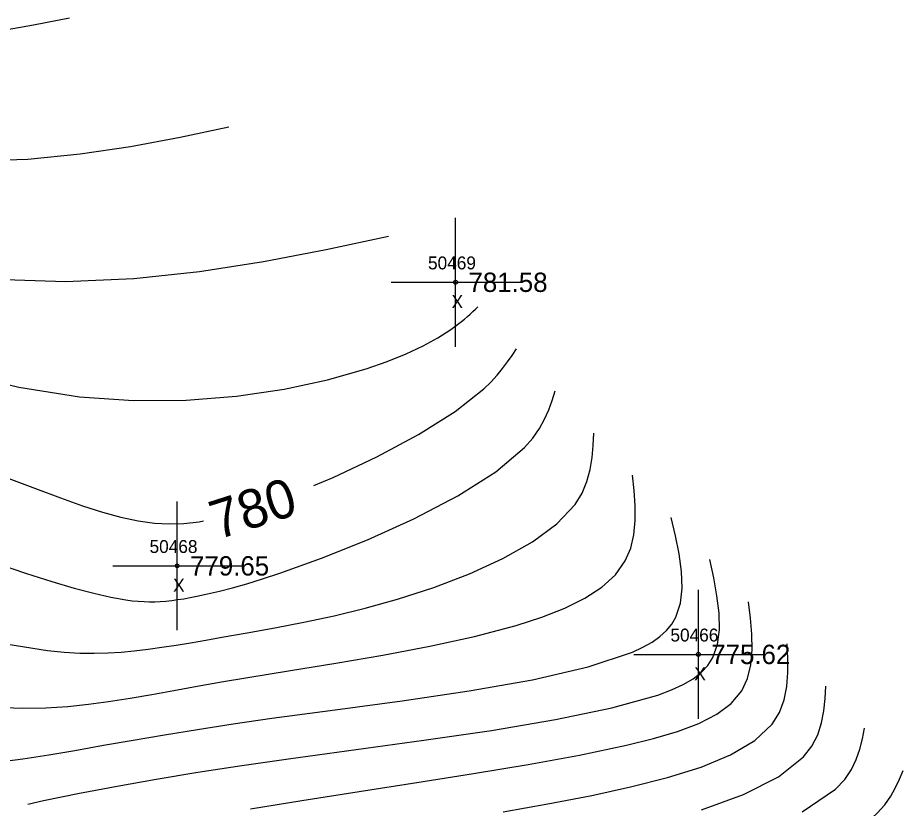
# Model space of a CAD drawing. Extents: x 1378535 to 1380697, y 997729 to 1000024.
# Drawn here: x 1379450.5 to 1379519.3, y 999255.8 to 999317.1 of the extents above; entities that cross this region are included whole.
import ezdxf

# ---------------------------------------------------------------- set-up
doc = ezdxf.new("R2010")
doc.units = 0
for name, color, linetype in [('RD_DTM_Major1', 7, 'Continuous'), ('RD_DTM_Major1_Lbl', 7, 'Continuous'), ('RD_DTM_Minor1', 7, 'Continuous'), ('RD_EX_Misc', 7, 'Continuous'), ('RD_EX_Misc_txCode', 7, 'Continuous'), ('RD_EX_TX_Misc_ELEV', 7, 'Continuous'), ('RD_SMD_Locator', 7, 'Continuous')]:
    doc.layers.add(name, color=color, linetype=linetype)

msp = doc.modelspace()

# ---------------------------------------------------------------- linework, layer by layer
at = {"layer": 'RD_DTM_Major1'}
for points in [[(1379473.511, 999280.806), (1379475.007, 999281.423), (1379478.414, 999283.027), (1379481.643, 999284.764), (1379484.48, 999286.551), (1379486.711, 999288.305), (1379487.261, 999288.841), (1379487.742, 999289.368), (1379488.168, 999289.886), (1379488.554, 999290.399), (1379488.911, 999290.909), (1379489.255, 999291.416)], [(1379445.979, 999282.807), (1379451.919, 999280.573), (1379453.855, 999279.857), (1379455.58, 999279.247), (1379457.135, 999278.743), (1379458.558, 999278.348), (1379459.889, 999278.065), (1379461.169, 999277.894), (1379462.299, 999277.839), (1379463.44, 999277.876), (1379464.611, 999278.004), (1379464.959, 999278.067)], [(1379451.323, 999256.11), (1379452.557, 999256.377), (1379455.348, 999256.947), (1379458.252, 999257.499), (1379461.298, 999258.038), (1379464.513, 999258.568), (1379467.927, 999259.093), (1379471.567, 999259.619), (1379482.041, 999261.05), (1379487.311, 999261.822), (1379492.265, 999262.653), (1379496.652, 999263.56), (1379500.218, 999264.562), (1379501.262, 999264.953), (1379502.168, 999265.368), (1379502.939, 999265.817), (1379503.58, 999266.311), (1379504.093, 999266.858), (1379504.483, 999267.469), (1379504.842, 999268.493), (1379504.985, 999269.649), (1379504.954, 999270.911), (1379504.793, 999272.252), (1379504.545, 999273.646), (1379504.253, 999275.066)], [(1379480.82, 999243.85), (1379481.655, 999244.004), (1379483.224, 999244.304), (1379484.868, 999244.629), (1379486.62, 999244.99), (1379491.785, 999246.124), (1379497.47, 999247.511), (1379503.228, 999249.107), (1379508.615, 999250.871), (1379513.185, 999252.761), (1379516.491, 999254.735), (1379517.23, 999255.392), (1379517.817, 999256.052), (1379518.282, 999256.716), (1379518.656, 999257.381), (1379518.969, 999258.048), (1379519.252, 999258.716)]]:
    msp.add_lwpolyline(points, dxfattribs=at)
at = {"layer": 'RD_DTM_Minor1'}
for points in [[(1379448.973, 999316.045), (1379451.781, 999316.552), (1379454.566, 999317.099)], [(1379447.1, 999305.987), (1379451.329, 999306.131), (1379455.384, 999306.531), (1379459.308, 999307.122), (1379463.145, 999307.841), (1379466.938, 999308.623)], [(1379448.717, 999296.812), (1379454.252, 999296.64), (1379459.549, 999296.865), (1379464.656, 999297.408), (1379469.62, 999298.188), (1379474.489, 999299.128), (1379479.31, 999300.147)], [(1379445.912, 999289.589), (1379450.634, 999288.449), (1379455.347, 999287.695), (1379459.526, 999287.402), (1379463.611, 999287.439), (1379467.531, 999287.754), (1379471.213, 999288.298), (1379474.583, 999289.019), (1379477.57, 999289.867), (1379479.22, 999290.442), (1379480.696, 999291.04), (1379482.004, 999291.654), (1379483.149, 999292.278), (1379484.138, 999292.904), (1379484.976, 999293.526), (1379485.212, 999293.721), (1379485.435, 999293.915), (1379485.649, 999294.108), (1379485.855, 999294.301), (1379486.057, 999294.493), (1379486.256, 999294.686)], [(1379449.003, 999274.74), (1379451.223, 999274.001), (1379453.189, 999273.376), (1379454.921, 999272.862), (1379456.443, 999272.455), (1379457.775, 999272.151), (1379458.939, 999271.945), (1379459.434, 999271.881), (1379459.901, 999271.836), (1379460.347, 999271.81), (1379460.775, 999271.799), (1379461.192, 999271.803), (1379461.602, 999271.821), (1379462.046, 999271.853), (1379462.493, 999271.9), (1379462.951, 999271.96), (1379463.424, 999272.035), (1379463.918, 999272.123), (1379464.44, 999272.226), (1379465.278, 999272.406), (1379466.198, 999272.624), (1379467.209, 999272.886), (1379468.32, 999273.2), (1379469.538, 999273.572), (1379470.872, 999274.008), (1379474.114, 999275.172), (1379477.673, 999276.602), (1379481.287, 999278.237), (1379484.699, 999280.014), (1379487.648, 999281.873), (1379489.874, 999283.75), (1379490.51, 999284.493), (1379491.016, 999285.23), (1379491.418, 999285.963), (1379491.74, 999286.693), (1379492.011, 999287.42), (1379492.255, 999288.146)], [(1379449.773, 999268.508), (1379452.868, 999268.012), (1379454.16, 999267.882), (1379455.362, 999267.813), (1379456.488, 999267.797), (1379457.555, 999267.825), (1379458.58, 999267.891), (1379459.579, 999267.986), (1379460.654, 999268.114), (1379461.732, 999268.265), (1379462.829, 999268.435), (1379463.958, 999268.624), (1379465.135, 999268.827), (1379466.374, 999269.044), (1379468.354, 999269.389), (1379470.482, 999269.772), (1379472.733, 999270.209), (1379475.085, 999270.716), (1379477.515, 999271.307), (1379479.998, 999271.998), (1379482.83, 999272.914), (1379485.592, 999273.967), (1379488.177, 999275.147), (1379490.476, 999276.444), (1379492.383, 999277.847), (1379493.789, 999279.347), (1379494.326, 999280.227), (1379494.704, 999281.129), (1379494.954, 999282.05), (1379495.107, 999282.984), (1379495.197, 999283.928), (1379495.255, 999284.876)], [(1379448.887, 999263.623), (1379450.898, 999263.549), (1379452.733, 999263.576), (1379454.433, 999263.684), (1379456.038, 999263.853), (1379457.59, 999264.066), (1379459.258, 999264.327), (1379460.941, 999264.612), (1379462.667, 999264.919), (1379464.466, 999265.244), (1379466.368, 999265.583), (1379468.402, 999265.933), (1379471.702, 999266.472), (1379475.235, 999267.043), (1379478.879, 999267.661), (1379482.508, 999268.342), (1379485.997, 999269.101), (1379489.223, 999269.954), (1379491.203, 999270.596), (1379492.983, 999271.299), (1379494.542, 999272.076), (1379495.859, 999272.938), (1379496.913, 999273.897), (1379497.683, 999274.965), (1379498.102, 999275.944), (1379498.345, 999276.993), (1379498.446, 999278.097), (1379498.441, 999279.244), (1379498.365, 999280.418), (1379498.254, 999281.606)], [(1379448.913, 999259.347), (1379450.944, 999259.607), (1379452.957, 999259.924), (1379454.975, 999260.273), (1379457.206, 999260.666), (1379459.512, 999261.069), (1379461.931, 999261.48), (1379464.503, 999261.899), (1379467.269, 999262.324), (1379470.266, 999262.756), (1379475.169, 999263.414), (1379480.374, 999264.112), (1379485.581, 999264.88), (1379490.493, 999265.745), (1379494.809, 999266.737), (1379498.231, 999267.883), (1379499.048, 999268.266), (1379499.759, 999268.671), (1379500.368, 999269.103), (1379500.877, 999269.568), (1379501.291, 999270.069), (1379501.613, 999270.612), (1379501.971, 999271.676), (1379502.101, 999272.862), (1379502.049, 999274.146), (1379501.86, 999275.502), (1379501.58, 999276.907), (1379501.254, 999278.336)], [(1379468.614, 999255.735), (1379472.585, 999256.386), (1379477.031, 999257.084), (1379481.506, 999257.776), (1379485.914, 999258.471), (1379490.159, 999259.18), (1379494.143, 999259.91), (1379497.77, 999260.672), (1379499.861, 999261.184), (1379501.744, 999261.739), (1379503.394, 999262.361), (1379504.79, 999263.075), (1379505.907, 999263.907), (1379506.724, 999264.882), (1379507.176, 999265.845), (1379507.43, 999266.911), (1379507.525, 999268.06), (1379507.501, 999269.271), (1379507.397, 999270.523), (1379507.253, 999271.796)], [(1379488.209, 999255.493), (1379491.683, 999256.119), (1379495.081, 999256.782), (1379498.092, 999257.434), (1379500.952, 999258.156), (1379503.57, 999258.977), (1379505.858, 999259.924), (1379507.724, 999261.024), (1379509.079, 999262.304), (1379509.641, 999263.214), (1379510.003, 999264.194), (1379510.206, 999265.229), (1379510.288, 999266.305), (1379510.29, 999267.408), (1379510.253, 999268.526)], [(1379503.59, 999255.656), (1379506.856, 999256.856), (1379509.561, 999258.221), (1379511.516, 999259.767), (1379512.161, 999260.607), (1379512.612, 999261.488), (1379512.908, 999262.401), (1379513.087, 999263.339), (1379513.189, 999264.294), (1379513.252, 999265.256)], [(1379511.41, 999255.501), (1379514.004, 999257.266), (1379514.704, 999258.016), (1379515.227, 999258.787), (1379515.608, 999259.573), (1379515.882, 999260.371), (1379516.084, 999261.176), (1379516.252, 999261.986)]]:
    msp.add_lwpolyline(points, dxfattribs=at)
at = {"layer": 'RD_EX_Misc'}
for p, q in [((1379484.519, 999291.579), (1379484.519, 999301.579)), ((1379479.519, 999296.579), (1379489.519, 999296.579)), ((1379462.917, 999269.581), (1379462.917, 999279.581)), ((1379457.917, 999274.581), (1379467.917, 999274.581)), ((1379503.351, 999262.715), (1379503.351, 999272.715)), ((1379498.351, 999267.715), (1379508.351, 999267.715))]:
    msp.add_line(p, q, dxfattribs=at)
at = {"layer": 'RD_SMD_Locator'}
for centre in [(1379484.519, 999296.579), (1379462.917, 999274.581), (1379503.351, 999267.715)]:
    msp.add_circle(centre, 0.15, dxfattribs=at)

# ---------------------------------------------------------------- texts
at = {"layer": 'RD_DTM_Major1_Lbl'}
msp.add_text('780', height=3, rotation=17.75834, dxfattribs=at).set_placement((1379466.049, 999276.6))
at = {"layer": 'RD_EX_Misc_txCode'}
for s, p in [('50469', (1379482.377, 999297.579)), ('X', (1379484.204, 999294.579)), ('50468', (1379460.775, 999275.581)), ('X', (1379462.602, 999272.581)), ('50466', (1379501.186, 999268.715)), ('X', (1379503.036, 999265.715))]:
    msp.add_text(s, height=1, dxfattribs=at).set_placement(p)
at = {"layer": 'RD_EX_TX_Misc_ELEV'}
for s, p in [('781.58', (1379485.519, 999295.829)), ('779.65', (1379463.917, 999273.831)), ('775.62', (1379504.351, 999266.965))]:
    msp.add_text(s, height=1.5, dxfattribs=at).set_placement(p)

doc.saveas('drawing.dxf')
